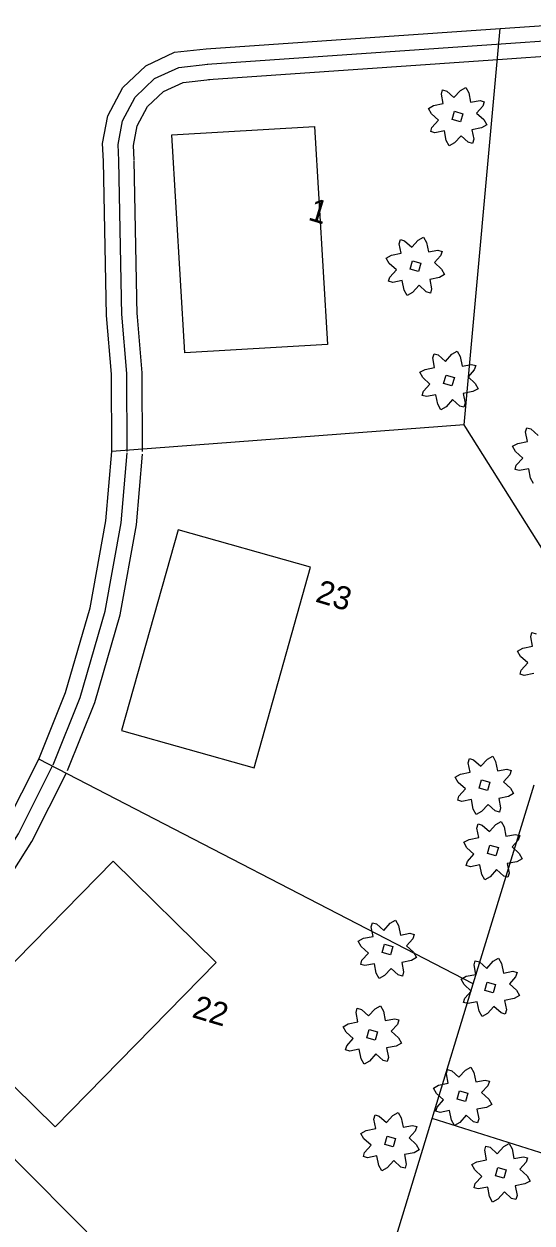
# Model space of a CAD drawing. Extents: x 1810019 to 1811399, y 1074962 to 1076105.
# Drawn here: x 1810548 to 1810680, y 1075531.7 to 1075843.3 of the extents above; entities that cross this region are included whole.
import ezdxf

# ---------------------------------------------------------------- set-up
doc = ezdxf.new("R2010")
doc.units = 0
for name, color, linetype in [('Environmental-New trees', 7, 'Continuous'), ('Property-Buildings', 7, 'Continuous'), ('Roadway-Land lines', 7, 'Continuous'), ('Roadway-Sidewalks', 7, 'Continuous'), ('Text-Property owner', 7, 'Continuous')]:
    doc.layers.add(name, color=color, linetype=linetype)

msp = doc.modelspace()

# ---------------------------------------------------------------- linework, layer by layer
at = {"layer": 'Environmental-New trees'}
for points in [[(1810653.68, 1075815.31), (1810653.98, 1075816.39), (1810655.67, 1075818.25), (1810653.81, 1075819.94), (1810653.03, 1075821.33), (1810654.39, 1075822.09), (1810656.89, 1075822.58), (1810656.42, 1075825.05), (1810656.73, 1075826.14), (1810657.81, 1075825.83), (1810659.67, 1075824.14), (1810661.36, 1075826), (1810662.75, 1075826.78), (1810663.53, 1075825.39), (1810664, 1075822.92), (1810666.47, 1075823.39), (1810667.56, 1075823.09), (1810667.19, 1075821.93), (1810665.56, 1075820.14), (1810667.42, 1075818.45), (1810668.2, 1075817.06), (1810666.85, 1075816.3), (1810664.34, 1075815.81), (1810664.81, 1075813.34), (1810664.51, 1075812.25), (1810663.42, 1075812.56), (1810661.56, 1075814.25), (1810659.87, 1075812.39), (1810658.48, 1075811.61), (1810657.7, 1075813), (1810657.23, 1075815.47), (1810654.76, 1075815)], [(1810659.84, 1075820.58), (1810662, 1075819.97), (1810661.39, 1075817.81), (1810659.23, 1075818.42)], [(1810642.72, 1075776.42), (1810643.02, 1075777.5), (1810644.72, 1075779.37), (1810642.86, 1075781.06), (1810642.08, 1075782.45), (1810643.43, 1075783.2), (1810645.94, 1075783.7), (1810645.47, 1075786.17), (1810645.77, 1075787.25), (1810646.85, 1075786.95), (1810648.72, 1075785.25), (1810650.41, 1075787.11), (1810651.8, 1075787.89), (1810652.58, 1075786.5), (1810653.05, 1075784.03), (1810655.52, 1075784.51), (1810656.6, 1075784.2), (1810656.23, 1075783.04), (1810654.6, 1075781.26), (1810656.46, 1075779.56), (1810657.24, 1075778.17), (1810655.89, 1075777.42), (1810653.38, 1075776.92), (1810653.86, 1075774.45), (1810653.55, 1075773.37), (1810652.47, 1075773.67), (1810650.61, 1075775.37), (1810648.91, 1075773.51), (1810647.52, 1075772.73), (1810646.75, 1075774.12), (1810646.27, 1075776.59), (1810643.8, 1075776.12)], [(1810648.88, 1075781.7), (1810651.05, 1075781.09), (1810650.44, 1075778.92), (1810648.27, 1075779.53)], [(1810651.46, 1075746.76), (1810651.76, 1075747.84), (1810653.45, 1075749.7), (1810651.59, 1075751.39), (1810650.82, 1075752.78), (1810652.17, 1075753.54), (1810654.67, 1075754.03), (1810654.2, 1075756.5), (1810654.51, 1075757.59), (1810655.59, 1075757.28), (1810657.45, 1075755.59), (1810659.14, 1075757.45), (1810660.53, 1075758.23), (1810661.31, 1075756.84), (1810661.78, 1075754.37), (1810664.25, 1075754.84), (1810665.34, 1075754.54), (1810664.97, 1075753.38), (1810663.34, 1075751.59), (1810665.2, 1075749.9), (1810665.98, 1075748.51), (1810664.63, 1075747.75), (1810662.12, 1075747.26), (1810662.59, 1075744.79), (1810662.29, 1075743.7), (1810661.2, 1075744.01), (1810659.34, 1075745.7), (1810657.65, 1075743.84), (1810656.26, 1075743.06), (1810655.48, 1075744.45), (1810655.01, 1075746.92), (1810652.54, 1075746.45)], [(1810657.62, 1075752.03), (1810659.79, 1075751.42), (1810659.17, 1075749.26), (1810657.01, 1075749.87)], [(1810660.67, 1075641.56), (1810660.97, 1075642.65), (1810662.67, 1075644.51), (1810660.81, 1075646.2), (1810660.03, 1075647.59), (1810661.38, 1075648.35), (1810663.89, 1075648.84), (1810663.41, 1075651.31), (1810663.72, 1075652.39), (1810664.8, 1075652.09), (1810666.66, 1075650.4), (1810668.36, 1075652.26), (1810669.75, 1075653.04), (1810670.52, 1075651.65), (1810671, 1075649.18), (1810673.47, 1075649.65), (1810674.55, 1075649.34), (1810674.18, 1075648.19), (1810672.55, 1075646.4), (1810674.41, 1075644.71), (1810675.19, 1075643.32), (1810673.84, 1075642.56), (1810671.33, 1075642.07), (1810671.8, 1075639.6), (1810671.5, 1075638.51), (1810670.42, 1075638.82), (1810668.55, 1075640.51), (1810666.86, 1075638.65), (1810665.47, 1075637.87), (1810664.69, 1075639.26), (1810664.22, 1075641.73), (1810661.75, 1075641.26)], [(1810666.83, 1075646.84), (1810669, 1075646.23), (1810668.39, 1075644.07), (1810666.22, 1075644.68)], [(1810662.89, 1075624.62), (1810663.19, 1075625.7), (1810664.88, 1075627.56), (1810663.02, 1075629.25), (1810662.25, 1075630.64), (1810663.6, 1075631.4), (1810666.11, 1075631.89), (1810665.63, 1075634.36), (1810665.94, 1075635.45), (1810667.02, 1075635.14), (1810668.88, 1075633.45), (1810670.57, 1075635.31), (1810671.96, 1075636.09), (1810672.74, 1075634.7), (1810673.21, 1075632.23), (1810675.69, 1075632.7), (1810676.77, 1075632.4), (1810676.4, 1075631.24), (1810674.77, 1075629.45), (1810676.63, 1075627.76), (1810677.41, 1075626.37), (1810676.06, 1075625.61), (1810673.55, 1075625.12), (1810674.02, 1075622.65), (1810673.72, 1075621.57), (1810672.63, 1075621.87), (1810670.77, 1075623.56), (1810669.08, 1075621.7), (1810667.69, 1075620.92), (1810666.91, 1075622.31), (1810666.44, 1075624.78), (1810663.97, 1075624.31)], [(1810669.05, 1075629.89), (1810671.22, 1075629.28), (1810670.61, 1075627.12), (1810668.44, 1075627.73)], [(1810635.45, 1075598.93), (1810635.75, 1075600.01), (1810637.44, 1075601.87), (1810635.58, 1075603.56), (1810634.81, 1075604.95), (1810636.16, 1075605.71), (1810638.67, 1075606.2), (1810638.19, 1075608.67), (1810638.5, 1075609.76), (1810639.58, 1075609.45), (1810641.44, 1075607.76), (1810643.14, 1075609.62), (1810644.52, 1075610.4), (1810645.3, 1075609.01), (1810645.77, 1075606.54), (1810648.25, 1075607.01), (1810649.33, 1075606.71), (1810648.96, 1075605.55), (1810647.33, 1075603.76), (1810649.19, 1075602.07), (1810649.97, 1075600.68), (1810648.62, 1075599.92), (1810646.11, 1075599.43), (1810646.58, 1075596.96), (1810646.28, 1075595.87), (1810645.19, 1075596.18), (1810643.33, 1075597.87), (1810641.64, 1075596.01), (1810640.25, 1075595.23), (1810639.47, 1075596.62), (1810639, 1075599.09), (1810636.53, 1075598.62)], [(1810641.61, 1075604.2), (1810643.78, 1075603.59), (1810643.17, 1075601.43), (1810641, 1075602.04)], [(1810662.19, 1075589.06), (1810662.5, 1075590.14), (1810664.19, 1075592), (1810662.33, 1075593.7), (1810661.55, 1075595.08), (1810662.9, 1075595.84), (1810665.41, 1075596.34), (1810664.94, 1075598.81), (1810665.24, 1075599.89), (1810666.33, 1075599.58), (1810668.19, 1075597.89), (1810669.88, 1075599.75), (1810671.27, 1075600.53), (1810672.05, 1075599.14), (1810672.52, 1075596.67), (1810674.99, 1075597.14), (1810676.07, 1075596.84), (1810675.71, 1075595.68), (1810674.08, 1075593.89), (1810675.94, 1075592.2), (1810676.71, 1075590.81), (1810675.36, 1075590.05), (1810672.86, 1075589.56), (1810673.33, 1075587.09), (1810673.02, 1075586.01), (1810671.94, 1075586.31), (1810670.08, 1075588.01), (1810668.39, 1075586.14), (1810667, 1075585.37), (1810666.22, 1075586.76), (1810665.75, 1075589.23), (1810663.27, 1075588.75)], [(1810668.35, 1075594.34), (1810670.52, 1075593.73), (1810669.91, 1075591.56), (1810667.74, 1075592.17)], [(1810631.52, 1075576.71), (1810631.82, 1075577.8), (1810633.52, 1075579.66), (1810631.66, 1075581.35), (1810630.88, 1075582.74), (1810632.23, 1075583.5), (1810634.74, 1075583.99), (1810634.27, 1075586.46), (1810634.57, 1075587.55), (1810635.65, 1075587.24), (1810637.52, 1075585.55), (1810639.21, 1075587.41), (1810640.6, 1075588.19), (1810641.37, 1075586.8), (1810641.85, 1075584.33), (1810644.32, 1075584.8), (1810645.4, 1075584.49), (1810645.03, 1075583.34), (1810643.4, 1075581.55), (1810645.26, 1075579.86), (1810646.04, 1075578.47), (1810644.69, 1075577.71), (1810642.18, 1075577.22), (1810642.66, 1075574.75), (1810642.35, 1075573.66), (1810641.27, 1075573.97), (1810639.41, 1075575.66), (1810637.71, 1075573.8), (1810636.32, 1075573.02), (1810635.55, 1075574.41), (1810635.07, 1075576.88), (1810632.6, 1075576.41)], [(1810637.68, 1075581.99), (1810639.85, 1075581.38), (1810639.24, 1075579.22), (1810637.07, 1075579.83)], [(1810655, 1075560.77), (1810655.3, 1075561.86), (1810657, 1075563.72), (1810655.14, 1075565.41), (1810654.36, 1075566.8), (1810655.71, 1075567.56), (1810658.22, 1075568.05), (1810657.75, 1075570.52), (1810658.05, 1075571.6), (1810659.13, 1075571.3), (1810660.99, 1075569.61), (1810662.69, 1075571.47), (1810664.08, 1075572.24), (1810664.85, 1075570.86), (1810665.33, 1075568.38), (1810667.8, 1075568.86), (1810668.88, 1075568.55), (1810668.51, 1075567.4), (1810666.88, 1075565.61), (1810668.74, 1075563.91), (1810669.52, 1075562.53), (1810668.17, 1075561.77), (1810665.66, 1075561.28), (1810666.14, 1075558.8), (1810665.83, 1075557.72), (1810664.75, 1075558.03), (1810662.89, 1075559.72), (1810661.19, 1075557.86), (1810659.8, 1075557.08), (1810659.03, 1075558.47), (1810658.55, 1075560.94), (1810656.08, 1075560.47)], [(1810661.16, 1075566.05), (1810663.33, 1075565.44), (1810662.72, 1075563.27), (1810660.55, 1075563.88)], [(1810636.14, 1075548.99), (1810636.44, 1075550.07), (1810638.14, 1075551.93), (1810636.28, 1075553.62), (1810635.5, 1075555.01), (1810636.85, 1075555.77), (1810639.36, 1075556.26), (1810638.89, 1075558.73), (1810639.19, 1075559.82), (1810640.27, 1075559.51), (1810642.13, 1075557.82), (1810643.83, 1075559.68), (1810645.22, 1075560.46), (1810645.99, 1075559.07), (1810646.47, 1075556.6), (1810648.94, 1075557.07), (1810650.02, 1075556.77), (1810649.65, 1075555.61), (1810648.02, 1075553.82), (1810649.88, 1075552.13), (1810650.66, 1075550.74), (1810649.31, 1075549.98), (1810646.8, 1075549.49), (1810647.28, 1075547.02), (1810646.97, 1075545.94), (1810645.89, 1075546.24), (1810644.03, 1075547.93), (1810642.33, 1075546.07), (1810640.94, 1075545.29), (1810640.17, 1075546.68), (1810639.69, 1075549.15), (1810637.22, 1075548.68)], [(1810642.3, 1075554.26), (1810644.47, 1075553.65), (1810643.86, 1075551.49), (1810641.69, 1075552.1)], [(1810664.93, 1075540.87), (1810665.24, 1075541.96), (1810666.93, 1075543.82), (1810665.07, 1075545.51), (1810664.29, 1075546.9), (1810665.64, 1075547.66), (1810668.15, 1075548.15), (1810667.68, 1075550.62), (1810667.98, 1075551.71), (1810669.07, 1075551.4), (1810670.93, 1075549.71), (1810672.62, 1075551.57), (1810674.01, 1075552.35), (1810674.79, 1075550.96), (1810675.26, 1075548.49), (1810677.73, 1075548.96), (1810678.82, 1075548.65), (1810678.45, 1075547.5), (1810676.82, 1075545.71), (1810678.68, 1075544.02), (1810679.46, 1075542.63), (1810678.1, 1075541.87), (1810675.6, 1075541.38), (1810676.07, 1075538.91), (1810675.76, 1075537.82), (1810674.68, 1075538.13), (1810672.82, 1075539.82), (1810671.13, 1075537.96), (1810669.74, 1075537.18), (1810668.96, 1075538.57), (1810668.49, 1075541.04), (1810666.02, 1075540.57)], [(1810671.1, 1075546.15), (1810673.26, 1075545.54), (1810672.65, 1075543.38), (1810670.49, 1075543.99)]]:
    msp.add_lwpolyline(points, close=True, dxfattribs=at)
for points in [[(1810680.37, 1075723.84), (1810679.59, 1075725.22), (1810679.12, 1075727.7), (1810676.65, 1075727.22), (1810675.56, 1075727.53), (1810675.87, 1075728.61), (1810677.56, 1075730.47), (1810675.7, 1075732.17), (1810674.92, 1075733.55), (1810676.28, 1075734.31), (1810678.78, 1075734.8), (1810678.31, 1075737.28), (1810678.61, 1075738.36), (1810679.7, 1075738.05), (1810681.56, 1075736.36)], [(1810680.44, 1075674.47), (1810677.97, 1075674), (1810676.88, 1075674.3), (1810677.19, 1075675.39), (1810678.88, 1075677.25), (1810677.02, 1075678.94), (1810676.24, 1075680.33), (1810677.6, 1075681.09), (1810680.1, 1075681.58), (1810679.63, 1075684.05), (1810679.94, 1075685.13), (1810681.02, 1075684.83)]]:
    msp.add_lwpolyline(points, dxfattribs=at)
at = {"layer": 'Property-Buildings'}
for points in [[(1810586.41, 1075814.46), (1810623.47, 1075816.65), (1810626.83, 1075760.01), (1810589.76, 1075757.81)], [(1810587.99, 1075711.8), (1810573.3, 1075659.67), (1810607.75, 1075649.96), (1810622.43, 1075702.1)], [(1810529.21, 1075583.03), (1810556.02, 1075556.72), (1810597.9, 1075599.4), (1810571.1, 1075625.71)]]:
    msp.add_lwpolyline(points, close=True, dxfattribs=at)
at = {"layer": 'Roadway-Land lines'}
for p, q in [((1810595.32, 1075836.84), (1810671.71, 1075842.13)), ((1810662.32, 1075739.15), (1810671.71, 1075842.13)), ((1810671.71, 1075842.13), (1810688.34, 1075843.28)), ((1810569.41, 1075767.54), (1810568.63, 1075807.62)), ((1810662.32, 1075739.15), (1810570.76, 1075732.19)), ((1810662.76, 1075738.45), (1810662.32, 1075739.15)), ((1810693.76, 1075689.12), (1810662.76, 1075738.45)), ((1810664.7, 1075593.84), (1810551.82, 1075652.29)), ((1810664.7, 1075593.84), (1810680.49, 1075645.61)), ((1810654.04, 1075558.89), (1810664.7, 1075593.84)), ((1810626.09, 1075467.25), (1810506.83, 1075587.28)), ((1810626.09, 1075467.25), (1810654.04, 1075558.89)), ((1810771, 1075521.77), (1810654.04, 1075558.89))]:
    msp.add_line(p, q, dxfattribs=at)
for points in [[(1810568.63, 1075807.62), (1810568.4, 1075812.21), (1810569.74, 1075819.44), (1810573.62, 1075826.74), (1810579.62, 1075832.43), (1810587.11, 1075835.91), (1810595.32, 1075836.84)], [(1810570.76, 1075732.19), (1810570.71, 1075752.31), (1810569.41, 1075767.54)], [(1810551.82, 1075652.29), (1810558.76, 1075669.58), (1810565.19, 1075691.59), (1810569.26, 1075714.15), (1810570.76, 1075732.19)], [(1810506.83, 1075587.28), (1810516.47, 1075597.47), (1810530.73, 1075615.43), (1810543.02, 1075634.79), (1810551.82, 1075652.29)]]:
    msp.add_lwpolyline(points, dxfattribs=at)
at = {"layer": 'Roadway-Sidewalks'}
for p, q in [((1810595.6, 1075832.85), (1810671.99, 1075838.14)), ((1810671.99, 1075838.14), (1810688.62, 1075839.29)), ((1810672.26, 1075834.15), (1810688.89, 1075835.3)), ((1810595.87, 1075828.86), (1810672.26, 1075834.15)), ((1810573.41, 1075767.62), (1810572.63, 1075807.69)), ((1810577.41, 1075767.7), (1810576.63, 1075807.77))]:
    msp.add_line(p, q, dxfattribs=at)
for points in [[(1810572.63, 1075807.82), (1810572.42, 1075811.95), (1810573.56, 1075818.11), (1810576.85, 1075824.29), (1810581.9, 1075829.08), (1810588.21, 1075832.01), (1810595.77, 1075832.86)], [(1810576.62, 1075808.02), (1810576.44, 1075811.68), (1810577.38, 1075816.77), (1810580.07, 1075821.83), (1810584.18, 1075825.72), (1810589.3, 1075828.11), (1810596.22, 1075828.89)], [(1810574.76, 1075732.2), (1810574.71, 1075752.48), (1810573.4, 1075767.88)], [(1810578.76, 1075732.21), (1810578.71, 1075752.66), (1810577.38, 1075768.22)], [(1810555.53, 1075650.8), (1810562.55, 1075668.27), (1810569.09, 1075690.67), (1810573.23, 1075713.63), (1810574.74, 1075731.86)], [(1810559.25, 1075649.31), (1810566.33, 1075666.96), (1810572.99, 1075689.75), (1810577.2, 1075713.11), (1810578.73, 1075731.53)], [(1810509.74, 1075584.53), (1810519.5, 1075594.85), (1810534, 1075613.11), (1810546.5, 1075632.81), (1810555.4, 1075650.49)], [(1810512.65, 1075581.78), (1810522.52, 1075592.23), (1810537.26, 1075610.78), (1810549.99, 1075630.84), (1810558.97, 1075648.69)]]:
    msp.add_lwpolyline(points, dxfattribs=at)

# ---------------------------------------------------------------- texts
at = {"layer": 'Text-Property owner'}
for s, p in [('1', (1810621.54, 1075792.45)), ('23', (1810623.43, 1075693.25)), ('22', (1810591.35, 1075585.28))]:
    msp.add_text(s, height=6, rotation=343.3561, dxfattribs=at).set_placement(p)

doc.saveas('drawing.dxf')
